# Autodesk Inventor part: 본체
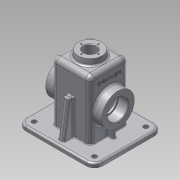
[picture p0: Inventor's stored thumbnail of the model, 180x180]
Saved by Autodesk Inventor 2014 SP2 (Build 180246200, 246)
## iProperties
Created: 2016-08
Part Number: 본체
Material: 알루미늄 6061
Document SubType Name: Modeling
Designer: user
Density: 2.71 g/cm^3
Appearance: 알루미늄 - 평지
Mass: 800.115 g
Surface Area: 912.153 cm^2
Volume: 295.245 cm^3
Author: user
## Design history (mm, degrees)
sketch "스케치1"
  geometry: L1 (-65, 57.5)-(65, 57.5); L2 (65, 57.5)-(65, -57.5); L3 (65, -57.5)-(-65, -57.5); L4 (-65, -57.5)-(-65, 57.5); L5 (-65, 57.5)-(65, -57.5); L6 (65, 57.5)-(-65, -57.5); 3 further points
  constraints: 12 end point, 3 midpoint, 2 parallel, 1 coincident, 1 horizontal alignment, 1 vertical
  dimensions: "d0" = 130 distance of L1.start L1.end; "d1" = 115 distance of L1.end L2.end
extrude "돌출1" new body sketch "스케치1" distance "d2" = 10; taper "d3" = 0 deg
sketch "스케치2"
  geometry: L1 (57.5, 0)-(-57.5, 0) reference; C1 r 27.5 at (0, 55); 2 further points
  constraints: 1 centre point, 1 midpoint, 1 vertical alignment
  dimensions: "d4" = 55 distance from line of L1 C1.centre; "d5" = 55 diameter of C1
extrude "돌출2" join sketch "스케치2" stored distance "d6" = 95; taper "d7" = 0 deg
sketch "스케치4"
  geometry: L1 (-65, 10)-(65, 10) reference; L2 (32.5, 10)-(32.5, 110); L3 (32.5, 110)-(-32.5, 110); L4 (-32.5, 110)-(-32.5, 10); L5 (65, 0)-(65, 10) reference; L6 (-65, 0)-(-65, 10) reference; 1 further point
  constraints: 6 end point, 2 point on line
  dimensions: "d14" = 65 distance of L2.end L3.end; "d15" = 32.5 distance between parallel lines of L5 L2; "d16" = 32.5 distance between parallel lines of L6 L4; "d17" = 100 distance from line of L2.start L3
extrude "돌출4" join sketch "스케치4" stored distance "d18" = 65; taper "d19" = 0 deg
sketch "스케치5"
  geometry: L1 (-42.5, 3)-(42.5, 3); L2 (42.5, 3)-(42.5, -3); L3 (42.5, -3)-(-42.5, -3); L4 (-42.5, -3)-(-42.5, 3); L5 (-42.5, 3)-(42.5, -3); L6 (42.5, 3)-(-42.5, -3); L7 (-65, -57.5)-(-65, 57.5) reference; L8 (65, 57.5)-(65, -57.5) reference; L9 (32.5, 3)-(32.5, -3); L10 (-32.5, -3)-(-32.5, 3); 1 further point
  constraints: 16 end point, 4 point on line, 4 vertical alignment, 2 horizontal alignment, 2 midpoint
  dimensions: "d21" = 6 distance of L3.end L1.start; "d22" = 10 distance between parallel lines of L4 L10; "d23" = 10 distance between parallel lines of L2 L9; "d24" = 22.5 distance between parallel lines of L4 L7
extrude "돌출5" join sketch "스케치5" stored distance "d25" = 65; taper "d26" = 0 deg
sketch "스케치6"
  geometry: L1 (47.5, 27.5)-(47.5, 82.5) reference; L2 (-47.5, 82.5)-(-47.5, 27.5) reference; L3 (65, 0)-(-65, 0) reference; L4 (47.5, 55)-(-47.5, 55); L5 (47.5, 72.5)-(30.5, 72.5); L6 (30.5, 72.5)-(30.5, 70); L7 (30.5, 70)-(-30.5, 70); L8 (-30.5, 70)-(-30.5, 72.5); L9 (-30.5, 72.5)-(-47.5, 72.5); L10 (47.5, 72.5)-(47.5, 55); L11 (-47.5, 55)-(-47.5, 72.5); 1 further point
  constraints: 16 end point, 2 horizontal, 2 midpoint, 2 point on line, 2 vertical, 1 horizontal alignment
  dimensions: "d28" = 35 diameter of L5.start L4; "d29" = 30 diameter of L7 L4; "d30" = 17 distance of L8.end L9.end; "d31" = 17 distance of L5.start L5.end
revolve "회전1" sketch "스케치6" stored, may be unused: angle "d32" = 90 deg
fillet "모깎기1" dims "d33" = 0.3
sketch "스케치7"
  geometry: L1 (65, 0)-(-65, 0) reference; L2 (27.5, 0)-(27.5, 105); L3 (27.5, 105)-(-27.5, 105); L4 (-27.5, 105)-(-27.5, 0); L5 (27.5, 0)-(-27.5, 0); L6 (32.5, 10)-(32.5, 110) reference; L7 (-32.5, 110)-(-32.5, 10) reference; 1 further point
  constraints: 8 end point, 2 point on line, 2 vertical alignment, 1 horizontal alignment
  dimensions: "d34" = 5 distance between parallel lines of L6 L2; "d35" = 5 distance between parallel lines of L7 L4; "d36" = 5 distance from line of L7.start L3
extrude "돌출6" cut sketch "스케치7" stored distance "d37" = 55; taper "d38" = 0 deg
fillet "모깎기2" dims "d39" = 3
fillet "모깎기3" dims "d40" = 3
node "작업 평면1"
sketch "스케치8"
  geometry: C1 r 20 at (32.5, -32.5); 1 further point
  constraints: 1 centre point, 1 coincident
  dimensions: "d42" = 40 diameter of C1
extrude "돌출7" join sketch "스케치8" stored distance "d43" = 55; taper "d44" = 7 deg
hole "구멍1" diameter "d47" = 21; stored, may be unused: countersink angle "d51" = 90 deg, drill point angle "d53" = 0 deg; dims "d45" = 10, "d46" = 10, "d48" = 6, "d49" = 4, "d50" = 2, "d52" = 8
chamfer "모따기1" distance "d54" = 1; stored, may be unused: second distance "d55" = 2, angle "d56" = 45 deg
sketch "스케치9"
  geometry: L1 (57.5, 10)-(-57.5, 10) reference; L2 (-32.5, 110)-(-32.5, 10) reference; L3 (32.5, 10)-(32.5, 110) reference; L4 (-49.5, 10)-(-41.068, 70); L5 (-57.5, 0)-(57.5, 0) reference; L6 (-57.5, 0)-(-57.5, 10) reference; L7 (-41.068, 70)-(-32.5, 70); L8 (49.5, 10)-(41.068, 70); L9 (41.068, 70)-(32.5, 70); L10 (57.5, 0)-(57.5, 10) reference; 1 further point
  constraints: 8 end point, 4 point on line, 1 horizontal alignment
  dimensions: "d58" = 8 deg angle of L6 L4; "d59" = 8 distance from line of L6 L4.start; "d61" = 70 vertical distance of L4.end L5.start; "d113" = 8 horizontal distance of L5.end L8.start; "d114" = 8 deg angle of L10 L8; "d115" = 70 distance between parallel lines of L5 L9
feature "리브1" sketch "스케치9" dims "d62" = 1, "d63" = 10, "d64" = 0, "d65" = 0, "d66" = 1, "d67" = 1
sketch "스케치10"
  geometry: C1 r 2 at (-21, 0); C2 r 2 at (0, 21); C3 r 2 at (0, -21); C4 r 2 at (21, 0); A1 r 21 centre (0, 0) between (-21, 0) and (0, 21); 1 further point
  constraints: 5 centre point, 4 point on circle, 3 equal radius, 2 horizontal alignment, 2 vertical alignment, 1 other
  dimensions: "d68" = 4 diameter of C1; "d69" = 42 diameter of A1
hole "구멍2" sketch "스케치10" at (-21, 0), (0, 21), (21, 0), (0, -21) diameter "d70" = 3.242; stored, may be unused: countersink angle "d74" = 90 deg, drill point angle "d76" = 118 deg; dims "d71" = 8, "d72" = 4, "d73" = 2, "d75" = 10
sketch "스케치11"
  geometry: C1 r 1.5 at (0, 14.5); C2 r 1.5 at (14.5, 0); C3 r 1.5 at (0, -14.5); C4 r 1.5 at (-14.5, 0); A1 r 14.5 centre (0, 0) between (0, 14.5) and (14.5, 0); 1 further point
  constraints: 5 centre point, 4 point on circle, 3 equal radius, 2 horizontal alignment, 2 vertical alignment, 1 coincident
  dimensions: "d77" = 3 diameter of C1; "d78" = 29 diameter of A1
hole "구멍3" sketch "스케치11" at (0, 14.5), (14.5, 0), (0, -14.5), (-14.5, 0) diameter "d79" = 2.459; stored, may be unused: countersink angle "d83" = 90 deg, drill point angle "d85" = 118 deg; dims "d80" = 7, "d81" = 4, "d82" = 2, "d84" = 9
sketch "스케치12"
  geometry: L1 (-10, 12.5)-(-10, 52.5) reference; L2 (100, 0)-(0, 0) reference; 2 further points
  constraints: 1 other
  dimensions: "d86" = 26 distance from line of L1 point (16, 32.5); "d87" = 32.5 distance from line of point (16, 32.5) L2
feature "엠보싱1" sketch "스케치12" dims "d0" = 130, "d1" = 115, "d14" = 65, "d15" = 32.5, "d16" = 32.5, "d17" = 100, "d88" = 0.5, "d89" = 0
fillet "모깎기4" dims "d90" = 14
fillet "모깎기5" dims "d91" = 3
sketch "스케치13"
  geometry: C1 r 4 at (-51, 43.5); C2 r 4 at (51, 43.5); C3 r 4 at (51, -43.5); C4 r 4 at (-51, -43.5); 1 further point
  constraints: 4 centre point, 3 equal radius, 2 horizontal alignment, 2 vertical alignment
  dimensions: "d92" = 8 diameter of C1; "d93" = 102 distance of C2.centre C1.centre; "d94" = 87 distance of C3.centre C2.centre; "d95" = 51 horizontal distance of point (0, 0) C1.centre; "d96" = 43.5 vertical distance of point (0, 0) C2.centre
hole "구멍4" sketch "스케치13" at (-51, 43.5), (51, 43.5), (51, -43.5), (-51, -43.5) diameter "d97" = 8; stored, may be unused: countersink angle "d101" = 90 deg, drill point angle "d103" = 118 deg; dims "d98" = 7, "d99" = 4, "d100" = 2, "d102" = 9
sketch "스케치14"
  geometry: L1 (51, 57.5)-(-51, 57.5) reference; L2 (65, -43.5)-(65, 43.5) reference; L3 (-51, -57.5)-(51, -57.5) reference; L4 (-65, 43.5)-(-65, -43.5) reference; L5 (51, 52.5)-(-51, 52.5); L6 (-60, 43.5)-(-60, -43.5); L7 (-51, -52.5)-(51, -52.5); L8 (60, -43.5)-(60, 43.5); A1 r 14 centre (51, 43.5) between (65, 43.5) and (51, 57.5) reference; A2 r 14 centre (51, -43.5) between (51, -57.5) and (65, -43.5) reference; A3 r 14 centre (-51, -43.5) between (-65, -43.5) and (-51, -57.5) reference; A4 r 14 centre (-51, 43.5) between (-51, 57.5) and (-65, 43.5) reference; A5 r 9 centre (-51, 43.5) between (-51, 52.5) and (-60, 43.5); A6 r 9 centre (-51, -43.5) between (-60, -43.5) and (-51, -52.5); A7 r 9 centre (51, -43.5) between (51, -52.5) and (60, -43.5); A8 r 9 centre (51, 43.5) between (60, 43.5) and (51, 52.5); 1 further point
  constraints: 8 end point, 8 point on circle, 4 centre point, 7 other
  dimensions: "d104" = 5 distance between parallel lines of L4 L6
extrude "돌출8" cut sketch "스케치14" distance "d105" = 3; taper "d106" = 0 deg
fillet "모깎기6" dims "d107" = 8
fillet "모깎기7" dims "d108" = 8
fillet "모깎기8" dims "d109" = 3
fillet "모깎기9" dims "d110" = 3
fillet "모깎기10" dims "d111" = 3
fillet "모깎기11" dims "d112" = 1
node "솔리드1"
mirror "대칭1"
mirror "대칭2"
